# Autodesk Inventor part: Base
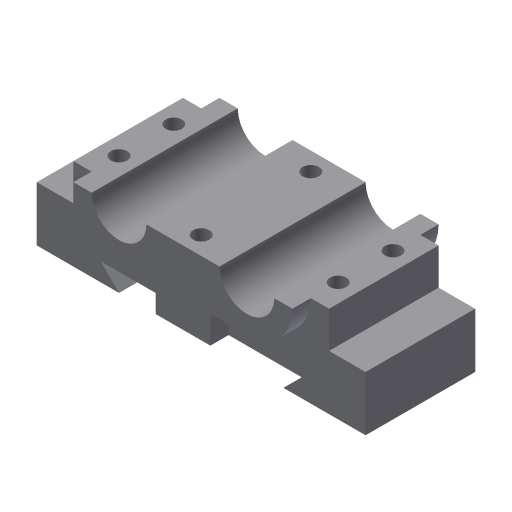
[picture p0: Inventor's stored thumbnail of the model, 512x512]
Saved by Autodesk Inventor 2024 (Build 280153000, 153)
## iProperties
Shininess: 77.0
Length Units: 11269
Angle Units: 11279
Time Units: 11290
Mass Units: 11283
Length Display Precision: 3
Angle Display Precision: 2
Created: 2002-02
Part Number: Base
Document SubType Name: Modeling
Designer: ***
Density: 1 g/cm^3
Material: Generic
Appearance: Default
Density: 0.0
Volumn: 0.0
Area: 0.0
PropertySet Name: Model Information
Control State: 0
Master: False
Checked Out: False
Author: ***
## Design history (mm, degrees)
sketch "Sketch2"
  geometry: L1 (-10.066, -1.263)-(24.934, -1.263); L2 (37.434, 11.237)-(32.434, 11.237); L3 (17.434, 11.237)-(-2.566, 11.237); L4 (-17.566, 11.237)-(-22.566, 11.237); A1 r 12.5 centre (-10.066, 11.237) between (-22.566, 11.237) and (-10.066, -1.263); A2 r 12.5 centre (24.934, 11.237) between (24.934, -1.263) and (37.434, 11.237); A3 r 7.5 centre (24.934, 11.237) between (17.434, 11.237) and (32.434, 11.237); A4 r 7.5 centre (-10.066, 11.237) between (-17.566, 11.237) and (-2.566, 11.237)
  constraints: 8 end point, 8 point on circle, 4 centre point, 3 horizontal, 3 parallel, 2 coincident, 2 equal radius, 2 tangent
  dimensions: "d0" = 12.5 radius of A1; "d1" = 7.5 radius of A4; "d2" = 35 distance of A1.centre A2.centre; "d3" = 12.5 distance between parallel lines of L3 L1
extrude "Extrusion1" new body sketch "Sketch2" stored distance "d4" = 40; taper "d5" = 0 deg
sketch "Sketch4"
  geometry: L1 (-27.566, 1.237)-(-37.566, 1.237); L2 (-37.566, 1.237)-(-37.566, -13.763); L3 (-37.566, -13.763)-(-15.066, -13.763); L4 (-15.066, -13.763)-(-20.066, -8.763); L5 (-20.066, -8.763)-(34.934, -8.763); L6 (34.934, -8.763)-(29.934, -13.763); L7 (29.934, -13.763)-(52.434, -13.763); L8 (52.434, -13.763)-(52.434, 1.237); L9 (52.434, 1.237)-(42.434, 1.237); L10 (24.934, -1.263)-(-10.066, -1.263); L11 (-17.566, 11.237)-(-22.566, 11.237) reference; L12 (37.434, 11.237)-(32.434, 11.237) reference; L13 (-22.566, 11.237)-(-27.566, 11.237); L14 (-27.566, 11.237)-(-27.566, 1.237); L15 (37.434, 11.237)-(42.434, 11.237); L16 (42.434, 11.237)-(42.434, 1.237); A1 r 12.5 centre (24.934, 11.237) between (24.934, -1.263) and (37.434, 11.237); A2 r 12.5 centre (-10.066, 11.237) between (-22.566, 11.237) and (-10.066, -1.263); A3 r 12.5 centre (24.934, 11.237) between (24.934, -1.263) and (37.434, 11.237) reference; A4 r 12.5 centre (-10.066, 11.237) between (-22.566, 11.237) and (-10.066, -1.263) reference
  constraints: 28 end point, 6 perpendicular, 5 equal length, 4 concentric, 4 parallel, 4 point on circle, 2 centre point, 2 collinear, 1 tangent
  dimensions: "d12" = 15 distance of L1.end L2.end; "d13" = 25 distance from line of L3 L11.end; "d14" = 90 distance between parallel lines of L2 L8; "d15" = 5 distance between parallel lines of L5 L7; "d16" = 22.5 distance of L2.end L3.end; "d24" = 5 distance of L12.start L15.end; "d25" = 15 distance from line of L8 L12.start
extrude "Extrusion3" join sketch "Sketch4" stored distance "d17" = 30; taper "d18" = 0 deg
sketch "Sketch5"
  geometry: L1 (-14.934, -1.263)-(0.066, -1.263); L2 (0.066, -1.263)-(0.066, -8.763); L3 (0.066, -8.763)-(-14.934, -8.763); L4 (-14.934, -8.763)-(-14.934, -1.263); L5 (10.066, -1.263)-(-24.934, -1.263) reference; 1 further point
  constraints: 8 end point, 2 parallel, 1 collinear, 1 horizontal, 1 perpendicular
  dimensions: "d19" = 7.5 distance of L1.end L2.end; "d20" = 15 distance of L2.end L3.end; "d21" = 15 distance from line of point (-29.934, -13.763) L4
extrude "Extrusion4" join sketch "Sketch5" distance "d22" = 40; taper "d23" = 0 deg
sketch "Sketch6"
  geometry: L1 (-5, -35)-(0, -35) reference; L2 (-5, -35)-(-5, -5) reference; 1 further point
  dimensions: "d26" = 7.5 distance from line of L1 point (0, -27.5); "d27" = 5 distance from line of L2 point (0, -27.5)
hole "Hole1" sketch "Sketch6" diameter "d28" = 4.5; stored, may be unused: countersink angle "d32" = 82 deg, drill point angle "d34" = 0 deg; dims "d29" = 6, "d30" = 4, "d31" = 2, "d33" = 15
pattern_linear "Rectangular Pattern1" dims "d37" = 60, "d40" = 15
sketch "Sketch7"
  geometry: L1 (-20, -40)-(-20, -35) reference; L2 (0, -40)-(20, -40) reference; 1 further point
  dimensions: "d41" = 30 distance from line of L1 point (10, -35); "d42" = 5 distance from line of L2 point (10, -35)
hole "Hole2" sketch "Sketch7" diameter "d43" = 4.5; stored, may be unused: countersink angle "d47" = 82 deg, drill point angle "d49" = 0 deg; dims "d44" = 6, "d45" = 4, "d46" = 2, "d48" = 15
pattern_linear "Rectangular Pattern2" dims "d52" = 30
body "Solid1"
